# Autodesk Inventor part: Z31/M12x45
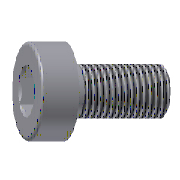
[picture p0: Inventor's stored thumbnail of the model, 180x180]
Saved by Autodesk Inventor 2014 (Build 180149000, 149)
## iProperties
Created: 2009-11
Part Number: Z31/M12x45
Material: Steel, Mild
Description: Hexagon Socket Head Cap Screw
Document SubType Name: Modeling
Designer: gaom
Standard Revision: 1
Manufacturer: HASCO
Language: en-US
Size Designation: M12x45
Categories: <MemberInstance><Categories><Category DisplayName="Mold" InternalName="349578f2-f4d4-4954-8c09-8e99297a61c0" Mnemonic="MOLD"><Category DisplayName="Fasteners" I
Mass: 0.133121 g
Surface Area: 2.01441 cm^2
Volume: 0.133121 cm^3
Density: 7.86 g/cm^3
Appearance: Steel
IsCustomPart: 0
Author: gaom
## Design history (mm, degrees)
body "Solid1"
revolve "Revolution1" stored, may be unused: angle "d44" = 90 deg
sketch "Sketch2"
  geometry: L1 (0, 5.774)-(5, 2.887); L2 (5, 2.887)-(5, -2.887); L3 (5, -2.887)-(0, -5.774); L4 (0, -5.774)-(-5, -2.887); L5 (-5, -2.887)-(-5, 2.887); L6 (-5, 2.887)-(0, 5.774); 3 further points
  constraints: 12 end point, 2 vertical alignment, 1 coincident, 14 other
extrude "Extrusion1" cut sketch "Sketch2" taper "d9" = 0 deg; stored distance "d45" = 10
thread "Thread1" dims "d10" = 39.8 (= b), "d11" = 0
chamfer "Chamfer1" distance "d12" = 0.875 (= 0.5 x P); stored, may be unused: second distance "d50" = 2, angle "d51" = 45 deg
fillet "Fillet1" dims "d13" = 0.875 (= 0.5 x P)
sketch "Sketch1"
  geometry: L1 (0, -56.4)-(0, 23.4) reference; L2 (5.774, 12)-(9, 12); L3 (9, 12)-(9, 0); L4 (9, 0)-(6, 0); L5 (6, 0)-(6, -45); L6 (6, -45)-(0, -45); L7 (0, 2.996)-(0, -45); L8 (0, 2.996)-(5, 6); L9 (5, 6)-(5, 11.226); L10 (5, 11.226)-(5.774, 12); 1 further point
  constraints: 18 end point, 4 vertical, 3 horizontal, 2 point on line
  dimensions: "d0" = 18 diameter of L3 L1 (= dk); "d1" = 12 distance between parallel lines of L4 L2 (= k); "d2" = 12 diameter of L5 L1 (= d); "d3" = 45 distance between parallel lines of L6 L4 (= L); "d4" = 59 deg angle of L1 L8; "d5" = 45 deg angle of L1 L10; "d6" = 10 diameter of L9 L1 (= sw); "d7" = 11.54701 diameter of L2.start L1 (= 1.1547 x sw); "d8" = 6 distance from line of L8.end L2 (= t)
other parameters: "d" = 12 [user parameter; used in 1 equation term], "L" = 45 [user parameter; used in 1 equation term], "dk" = 18 [user parameter; used in 1 equation term], "b" = 39.8 [user parameter; used in 1 equation term], "k" = 12 [user parameter; used in 1 equation term], "sw" = 10 [user parameter; used in 2 equation terms], "t" = 6 [user parameter; used in 1 equation term], "P" = 1.75 [user parameter; used in 2 equation terms], "d14" = 0, "d15" = 0, "d55" = 0
